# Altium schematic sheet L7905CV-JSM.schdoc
size 127 x 101 mm
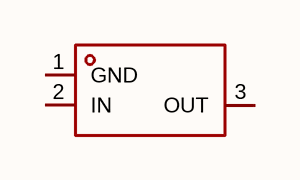
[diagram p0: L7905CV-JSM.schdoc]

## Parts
U?  l7905cv-jsm  [TO-220-3_L10.0-W4.6-P2.54-L]  (value not drawn)

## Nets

Not connected (* = marked no-connect by the designer): U? 1(GND) 2(IN) 3(OUT)

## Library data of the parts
U? = l7905cv-jsm: 输出极性:负极;工作电压:35V;输出电压:5V;输出电流:1.5A;电源纹波抑制比(PSRR):-;输出类型:固定;; Manufacturer: JSMSEMI(杰盛微); AddInBom: yes; ModelId: 711528d35a164a8f8c6ce62cc2c792eb; ModelTransform: 401.574,178.58232,0,0,0,0,0,26.575,-196.85; Output Configuration: 负极; Voltage - Supply: 35V; Output Voltage: 5V; Output Current: 1.5A; standby current: 6mA; Output Type: 固定; Number of Outputs: 1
